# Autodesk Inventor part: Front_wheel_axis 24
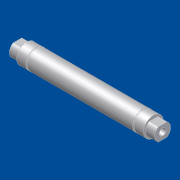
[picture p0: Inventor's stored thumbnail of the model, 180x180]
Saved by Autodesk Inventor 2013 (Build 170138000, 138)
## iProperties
Shininess: 69.0
Length Units: 11269
Angle Units: 11279
Time Units: 11290
Mass Units: 11283
Length Display Precision: 3
Angle Display Precision: 2
Created: 2001-04
Part Number: Front_wheel_axis 24
Material: Standard
Document SubType Name: Modellieren
Designer: dl
Density: 1 g/cm^3
Density: 0.0
Volumn: 0.0
Area: 0.0
PropertySet Name: Model Information
Control State: 0
Master: False
Checked Out: False
Author: dl
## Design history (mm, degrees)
body "Solid1"
sketch "Sketch2"
  geometry: C1 r 6 at (0, 0) reference; 1 further point
  constraints: 1 coincident
sketch "Sketch3"
  geometry: L1 (7, 4.706)-(0, 4.706); L2 (0, 4.706)-(0, 7.706); L3 (0, 7.706)-(7, 7.706); L4 (7, 7.706)-(7, 4.706); L5 (110, 4.706)-(103, 4.706); L6 (103, 4.706)-(103, 7.706); L7 (103, 7.706)-(110, 7.706); L8 (110, 7.706)-(110, 4.706); L9 (110, -6.294)-(110, 5.706) reference; L10 (103, -7.794)-(103, 7.206) reference; L11 (7, -6.294)-(7, 5.706) reference; L12 (0, -6.294)-(0, 5.706) reference; L13 (0, -0.294)-(7.96, -0.294)
  constraints: 18 end point, 4 parallel, 3 perpendicular, 2 horizontal, 1 midpoint
  dimensions: "d20" = 3 distance of L3.end L1.start; "d21" = 3 distance of L5.end L6.end (= d20); "d22" = 0 distance between parallel lines of L9 L8; "d23" = 0 distance from line of L10 L6.end; "d24" = 0 distance from line of L11 L3.end; "d25" = 0 distance between parallel lines of L12 L2; "d26" = 5 distance between parallel lines of L13 L1; "d27" = 0 distance between parallel lines of L5 L1
extrude "Extrusion1" cut sketch "Sketch3" stored distance "d28" = 20; taper "d29" = 0 deg
revolve "Revolution1" stored, may be unused: angle "d12" = 90 deg
hole "Hole1" sketch "Sketch2" diameter "d13" = 5.2; stored, may be unused: countersink angle "d17" = 60 deg, drill point angle "d19" = 118 deg; dims "d14" = 6, "d15" = 4, "d16" = 2, "d18" = 8
pattern_circular "Circular Pattern1" dims angle "d32" = 360 deg
sketch "Sketch1"
  geometry: L1 (0, -0.294)-(0, 5.706); L2 (0, 5.706)-(7, 5.706); L3 (7, 5.706)-(7, 7.206); L4 (7, 7.206)-(14, 7.206); L5 (14, 7.206)-(14, 6.856); L6 (14, 6.856)-(15.2, 6.856); L7 (15.2, 6.856)-(15.2, 7.206); L8 (15.2, 7.206)-(94.8, 7.206); L9 (94.8, 7.206)-(94.8, 6.856); L10 (94.8, 6.856)-(96, 6.856); L11 (96, 6.856)-(96, 7.206); L12 (96, 7.206)-(103, 7.206); L13 (103, 7.206)-(103, 5.706); L14 (103, 5.706)-(110, 5.706); L15 (110, 5.706)-(110, -0.294); L16 (110, -0.294)-(0, -0.294)
  constraints: 32 end point, 13 parallel, 7 collinear, 1 perpendicular, 1 vertical
  dimensions: "d3" = 6 distance of L1.start L1.end; "d4" = 7.15 distance from line of L16 L9.end; "d5" = 7.5 distance between parallel lines of L16 L4; "d6" = 7 distance of L1.end L2.end; "d7" = 1.2 distance of L5.end L6.end; "d8" = 82 distance of L4.end L11.end; "d9" = 110 distance of L15.end L1.start; "d10" = 96 distance of L12.end L3.end (derived); "d11" = 7 distance of L11.end L12.end
other parameters: "d35" = 0
